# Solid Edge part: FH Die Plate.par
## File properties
Author: Dave
Template: Normal.par
Last saved by: Dave
Revision: 10
Application: Solid Edge
Accuracy: 0.990
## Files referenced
..\Mould Assy.asm
EC:\drawings\DK laminates\Squared Leg Foot\ToolDrawings\Mould Assy.asm
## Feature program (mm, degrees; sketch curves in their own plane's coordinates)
boolean "unnamed Boolean 1"
sketch for "unnamed Cutout 1" plane through (0, 0, 0) normal (0, 0, 1) x-axis (1, 0, 0)
extrude "unnamed Cutout 1" cut through along -normal
sketch for "Hole_3" plane through (0, 0, -46) normal (0, 0, -1) x-axis (-1, 0, 0)
  hole centre (70, 70) bore radius 10
hole "Hole_3" diameter 20 through  CounterBoreDepth = 4 mm; VBottomAngle = 118 deg
sketch for "unnamed Hole 1" plane through (0, 0, -46) normal (0, 0, -1) x-axis (-1, 0, 0)
hole "unnamed Hole 1" through
sketch for "unnamed Hole 2" plane through (0, 0, -46) normal (0, 0, -1) x-axis (-1, 0, 0)
  hole centre (-70, -70) bore radius 10
hole "unnamed Hole 2" through
sketch for "unnamed Hole 3" plane through (0, 0, -46) normal (0, 0, -1) x-axis (-1, 0, 0)
hole "unnamed Hole 3" through
sketch for "Hole_7" plane through (0, 0, -46) normal (0, 0, -1) x-axis (0, -1, 0)
  hole centre (-45, 74.5) bore radius 4.188
hole "Hole_7" finite  VBottomAngle = 118 deg; ThreadDepth = 20 mm
sketch for "unnamed Hole 4" plane through (0, 0, -46) normal (0, 0, -1) x-axis (0, -1, 0)
  hole centre (45, 74.5) bore radius 4.188
hole "unnamed Hole 4" finite
sketch for "unnamed Hole 5" plane through (0, 0, -46) normal (0, 0, -1) x-axis (0, -1, 0)
  hole centre (45, -74.5) bore radius 4.188
hole "unnamed Hole 5" finite
sketch for "unnamed Hole 6" plane through (0, 0, -46) normal (0, 0, -1) x-axis (0, -1, 0)
  hole centre (-45, -74.5) bore radius 4.188
  dimension (linear) = 45
hole "unnamed Hole 6" finite
pattern "unnamed Pattern 1" of "Hole_3", "unnamed Hole 1", "unnamed Hole 2", "unnamed Hole 3"
pattern "unnamed Pattern 2" of "Hole_7", "unnamed Hole 4", "unnamed Hole 5", "unnamed Hole 6"
sketch for "unnamed Protrusion 1" plane through (0, 0, 0) normal (0, 0, 1) x-axis (1, 0, 0)
  line (-87.5, -87.5) -> (87.5, -87.5)
  line (87.5, -87.5) -> (87.5, 87.5)
  line (87.5, 87.5) -> (-87.5, 87.5)
  line (-87.5, 87.5) -> (-87.5, -87.5)
  dimension (linear) = 87.5
  dimension (linear) = 87.5
extrude "unnamed Protrusion 1" add finite 46 along -normal
sketch for "Hole_1" plane through (0, 0, 0) normal (0, 0, 1) x-axis (1, 0, 0)
  hole centre (0, 0) bore radius 7
hole "Hole_1" diameter 14 through  VBottomAngle = 118 deg
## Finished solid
Body 1: solid body, 252 faces, 528 edges, 282 vertices.
  Faces by surface: cylinder 102, spline 48, plane 43, sphere 38, torus 16, cone 5
  Edges by curve: line 200, circle 168, curve on surface 124, ellipse 26, spline 10
Body 2: solid body, 74 faces, 147 edges, 72 vertices.
  Faces by surface: cylinder 33, plane 22, sphere 6, spline 6, cone 4, torus 3
  Edges by curve: line 67, circle 56, curve on surface 18, ellipse 6
Bounding box of the edges (mm; curved faces can reach further): 175.000 x 175.000 x 60.620, from (-87.5, -87.5, -46) to (87.5, 87.5, 14.62).
Cylindrical faces by radius (mm): R0.504 x113, R1.008 x7, R4.188 x4, R4.2235 x1, R7 x1, R7.2475 x1, R10 x4, R12 x4
Conical faces (half-angle, radius in mm at the cone's reference point): 1 deg R7.056 x1, 1 deg R20.412 x1, 1 deg R23.436 x3, 59 deg R4.188 x4
Toroidal faces (ring radius, tube radius in mm): R0.504 r0.504 x5, R1.512 r0.504 x2, R6.1209 r0.504 x1, R6.7435 r0.504 x1, R7.5513 r0.504 x1, R7.7515 r0.504 x1, R19.9167 r0.504 x1, R21.1184 r0.504 x1, R22.7296 r0.504 x3, R23.9313 r0.504 x3
Spherical faces by radius (mm): R0.504 x44
Planar faces by outward normal: +x 4, +y 4, +z 10, -x 4, -y 4, -z 8, oblique 31
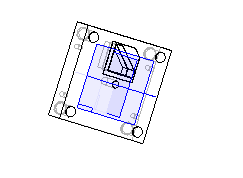
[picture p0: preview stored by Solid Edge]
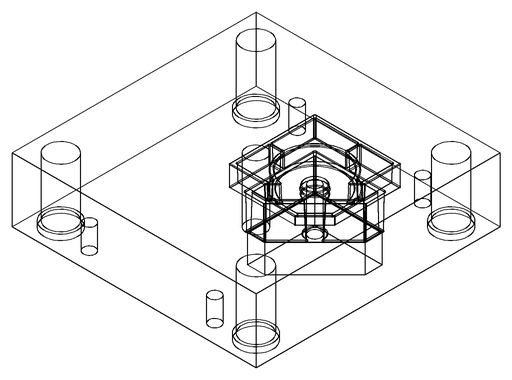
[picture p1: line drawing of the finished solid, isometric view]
